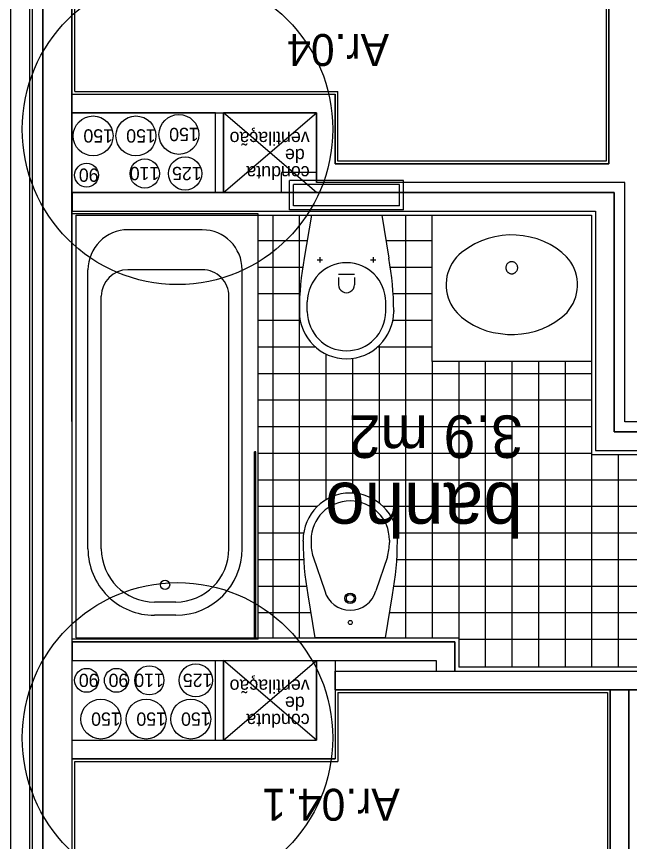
# Model space of a CAD drawing. Extents: x 1278 to 1356, y -253.7 to -224.
# Drawn here: x 1340.025 to 1342.332, y -240.985 to -237.882 of the extents above; entities that cross this region are included whole.
import ezdxf

# ---------------------------------------------------------------- set-up
doc = ezdxf.new("R2010")
doc.units = 0
for name, color, linetype in [('Level 1', 7, 'Continuous'), ('Level 10', 7, 'Continuous'), ('Level 11', 7, 'Continuous'), ('Level 2', 7, 'Continuous'), ('Level 36', 7, 'Continuous'), ('Level 40', 7, 'Continuous'), ('Level 41', 7, 'Continuous'), ('Level 60', 7, 'Continuous'), ('Level 65', 7, 'Continuous'), ('Level 66', 7, 'Continuous'), ('Level 67', 7, 'Continuous'), ('Level 69', 7, 'Continuous'), ('Level 70', 7, 'Continuous')]:
    doc.layers.add(name, color=color, linetype=linetype)

msp = doc.modelspace()

# ---------------------------------------------------------------- linework, layer by layer
at = {"layer": 'Level 1'}
for p, q in [((1340.2341, -246.584), (1340.234, -232.2657)), ((1342.254, -236.6557), (1342.254, -238.4357)), ((1340.0733, -236.7713), (1340.0733, -242.1713)), ((1340.124, -242.1713), (1340.124, -236.7713)), ((1340.234, -238.174), (1341.224, -238.174)), ((1340.234, -238.244), (1341.154, -238.244)), ((1340.774, -238.544), (1340.774, -238.244)), ((1340.804, -238.544), (1340.804, -238.244)), ((1342.254, -238.4357), (1341.224, -238.4357)), ((1341.154, -238.469), (1341.0217, -238.469)), ((1341.154, -238.499), (1341.0517, -238.499)), ((1342.314, -238.5057), (1341.154, -238.5057)), ((1342.314, -239.4057), (1342.314, -238.5057)), ((1340.234, -238.544), (1342.274, -238.544)), ((1342.274, -238.544), (1342.274, -239.444)), ((1340.234, -238.614), (1342.204, -238.614)), ((1342.204, -238.614), (1342.204, -239.514)), ((1343.314, -239.4057), (1342.314, -239.4057)), ((1342.274, -239.444), (1343.274, -239.444)), ((1342.204, -239.514), (1343.204, -239.514)), ((1340.234, -240.234), (1341.674, -240.234)), ((1341.674, -240.234), (1341.674, -240.344)), ((1340.234, -240.304), (1341.154, -240.304)), ((1340.774, -240.604), (1340.774, -240.304)), ((1340.804, -240.604), (1340.804, -240.304)), ((1341.224, -240.304), (1341.604, -240.304)), ((1341.604, -240.304), (1341.604, -240.344)), ((1341.224, -240.414), (1342.259, -240.414)), ((1342.259, -240.414), (1342.259, -242.194)), ((1342.329, -242.194), (1342.329, -240.414)), ((1342.329, -240.414), (1342.439, -240.414)), ((1340.234, -240.604), (1341.154, -240.604)), ((1340.2333, -240.674), (1341.224, -240.674))]:
    msp.add_line(p, q, dxfattribs=at)
for points in [[(1341.224, -238.4357), (1341.224, -238.174)], [(1341.154, -238.244), (1341.154, -238.5057)], [(1341.154, -240.304), (1341.154, -240.604)], [(1341.224, -240.304), (1341.224, -240.344)], [(1341.224, -240.414), (1341.224, -240.674)]]:
    msp.add_lwpolyline(points, dxfattribs=at)
at = {"layer": 'Level 10'}
for p, q in [((1340.989, -238.629), (1340.989, -240.219)), ((1341.089, -238.629), (1341.089, -240.219)), ((1341.489, -238.629), (1341.489, -240.219)), ((1340.934, -238.724), (1341.1188, -238.724)), ((1341.4146, -238.724), (1341.589, -238.724)), ((1340.934, -238.824), (1341.102, -238.824)), ((1341.4314, -238.824), (1341.589, -238.824)), ((1340.934, -238.924), (1341.0912, -238.924)), ((1341.4423, -238.924), (1341.589, -238.924)), ((1340.934, -239.024), (1341.0922, -239.024)), ((1341.4412, -239.024), (1341.589, -239.024)), ((1340.934, -239.124), (1341.1486, -239.124)), ((1341.3848, -239.124), (1341.589, -239.124)), ((1341.389, -239.1201), (1341.389, -239.7109)), ((1341.189, -239.1511), (1341.189, -239.6995)), ((1341.289, -239.1676), (1341.289, -239.6742)), ((1341.589, -239.179), (1341.589, -240.219)), ((1341.689, -239.179), (1341.689, -240.219)), ((1341.789, -239.179), (1341.789, -240.329)), ((1341.889, -239.179), (1341.889, -240.329)), ((1341.989, -239.179), (1341.989, -240.329)), ((1342.089, -239.179), (1342.089, -240.329)), ((1340.934, -239.224), (1342.189, -239.224)), ((1340.934, -239.324), (1342.189, -239.324)), ((1340.934, -239.424), (1342.189, -239.424)), ((1340.934, -239.524), (1342.189, -239.524)), ((1342.189, -239.529), (1342.189, -240.329)), ((1342.289, -239.529), (1342.289, -240.329)), ((1340.934, -239.624), (1343.189, -239.624)), ((1340.934, -239.724), (1341.1572, -239.724)), ((1341.4042, -239.724), (1343.189, -239.724)), ((1340.934, -239.824), (1341.1035, -239.824)), ((1341.4578, -239.824), (1343.099, -239.824)), ((1340.934, -239.924), (1341.1054, -239.924)), ((1341.456, -239.924), (1343.099, -239.924)), ((1340.934, -240.024), (1341.1162, -240.024)), ((1341.4452, -240.024), (1343.099, -240.024)), ((1340.934, -240.124), (1341.1328, -240.124)), ((1341.4286, -240.124), (1343.099, -240.124)), ((1341.689, -240.224), (1343.099, -240.224))]:
    msp.add_line(p, q, dxfattribs=at)
at = {"layer": 'Level 11'}
for p, q in [((1341.0517, -238.609), (1341.0517, -238.499)), ((1341.4817, -238.499), (1341.0517, -238.499)), ((1341.4667, -238.514), (1341.0667, -238.514)), ((1341.0667, -238.594), (1341.0667, -238.514)), ((1341.4667, -238.594), (1341.4667, -238.514)), ((1341.4817, -238.609), (1341.4817, -238.499)), ((1341.4817, -238.609), (1341.0517, -238.609)), ((1341.4667, -238.594), (1341.0667, -238.594)), ((1340.934, -238.624), (1340.234, -238.624)), ((1340.234, -240.224), (1340.234, -238.624)), ((1340.234, -240.229), (1340.234, -238.629)), ((1340.934, -240.224), (1340.934, -238.624)), ((1341.1344, -238.629), (1341.1077, -238.791)), ((1341.1344, -238.629), (1341.399, -238.629)), ((1341.399, -238.629), (1341.4257, -238.791)), ((1340.724, -238.684), (1340.444, -238.684)), ((1341.8518, -238.7055), (1341.8253, -238.7099)), ((1341.8784, -238.7034), (1341.8518, -238.7055)), ((1341.9051, -238.7037), (1341.8784, -238.7034)), ((1341.9316, -238.7063), (1341.9051, -238.7037)), ((1341.9578, -238.7113), (1341.9316, -238.7063)), ((1341.75, -238.7367), (1341.7268, -238.75)), ((1341.7743, -238.7256), (1341.75, -238.7367)), ((1341.7995, -238.7166), (1341.7743, -238.7256)), ((1341.8253, -238.7099), (1341.7995, -238.7166)), ((1341.9837, -238.7185), (1341.9578, -238.7113)), ((1342.0087, -238.728), (1341.9837, -238.7185)), ((1342.0327, -238.7397), (1342.0087, -238.728)), ((1341.6997, -238.7691), (1341.6897, -238.7779)), ((1341.7268, -238.75), (1341.6997, -238.7691)), ((1342.0557, -238.7534), (1342.0327, -238.7397)), ((1342.0774, -238.7691), (1342.0557, -238.7534)), ((1342.0946, -238.7851), (1342.0774, -238.7691)), ((1341.1567, -238.7972), (1341.1767, -238.7972)), ((1341.1667, -238.7872), (1341.1667, -238.8072)), ((1341.3567, -238.7972), (1341.3767, -238.7972)), ((1341.3667, -238.7872), (1341.3667, -238.8072)), ((1341.672, -238.7978), (1341.6645, -238.8089)), ((1341.6804, -238.7874), (1341.672, -238.7978)), ((1341.6897, -238.7779), (1341.6804, -238.7874)), ((1342.1032, -238.7953), (1342.0946, -238.7851)), ((1342.1109, -238.8062), (1342.1032, -238.7953)), ((1341.658, -238.8206), (1341.6525, -238.8328)), ((1341.6645, -238.8089), (1341.658, -238.8206)), ((1341.8663, -238.8248), (1341.8662, -238.8267)), ((1341.8662, -238.8267), (1341.8663, -238.8287)), ((1341.8666, -238.8228), (1341.8663, -238.8248)), ((1341.8663, -238.8287), (1341.8666, -238.8307)), ((1341.867, -238.8209), (1341.8666, -238.8228)), ((1341.8666, -238.8307), (1341.867, -238.8326)), ((1341.8676, -238.819), (1341.867, -238.8209)), ((1341.8683, -238.8172), (1341.8676, -238.819)), ((1341.8692, -238.8155), (1341.8683, -238.8172)), ((1341.8703, -238.8138), (1341.8692, -238.8155)), ((1341.8715, -238.8122), (1341.8703, -238.8138)), ((1341.8728, -238.8108), (1341.8715, -238.8122)), ((1341.8742, -238.8095), (1341.8728, -238.8108)), ((1341.8758, -238.8083), (1341.8742, -238.8095)), ((1341.8774, -238.8072), (1341.8758, -238.8083)), ((1341.8791, -238.8063), (1341.8774, -238.8072)), ((1341.8809, -238.8055), (1341.8791, -238.8063)), ((1341.8828, -238.8049), (1341.8809, -238.8055)), ((1341.8847, -238.8045), (1341.8828, -238.8049)), ((1341.8866, -238.8043), (1341.8847, -238.8045)), ((1341.8885, -238.8042), (1341.8866, -238.8043)), ((1341.8905, -238.8043), (1341.8885, -238.8042)), ((1341.8924, -238.8045), (1341.8905, -238.8043)), ((1341.8943, -238.8049), (1341.8924, -238.8045)), ((1341.8962, -238.8055), (1341.8943, -238.8049)), ((1341.898, -238.8063), (1341.8962, -238.8055)), ((1341.8997, -238.8072), (1341.898, -238.8063)), ((1341.9013, -238.8083), (1341.8997, -238.8072)), ((1341.9029, -238.8095), (1341.9013, -238.8083)), ((1341.9043, -238.8108), (1341.9029, -238.8095)), ((1341.9056, -238.8122), (1341.9043, -238.8108)), ((1341.9068, -238.8138), (1341.9056, -238.8122)), ((1341.9079, -238.8155), (1341.9068, -238.8138)), ((1341.9088, -238.8172), (1341.9079, -238.8155)), ((1341.9095, -238.819), (1341.9088, -238.8172)), ((1341.9101, -238.8209), (1341.9095, -238.819)), ((1341.9105, -238.8228), (1341.9101, -238.8209)), ((1341.9101, -238.8326), (1341.9105, -238.8307)), ((1341.9108, -238.8248), (1341.9105, -238.8228)), ((1341.9105, -238.8307), (1341.9108, -238.8287)), ((1341.9109, -238.8267), (1341.9108, -238.8248)), ((1341.9108, -238.8287), (1341.9109, -238.8267)), ((1342.1177, -238.8177), (1342.1109, -238.8062)), ((1342.1234, -238.8298), (1342.1177, -238.8177)), ((1342.1281, -238.8424), (1342.1234, -238.8298)), ((1340.294, -239.884), (1340.294, -238.834)), ((1340.724, -238.834), (1340.444, -238.834)), ((1340.874, -239.884), (1340.874, -238.834)), ((1341.2367, -238.8512), (1341.2967, -238.8512)), ((1341.6448, -238.8584), (1341.6426, -238.8716)), ((1341.6481, -238.8454), (1341.6448, -238.8584)), ((1341.6525, -238.8328), (1341.6481, -238.8454)), ((1341.867, -238.8326), (1341.8676, -238.8345)), ((1341.8676, -238.8345), (1341.8683, -238.8363)), ((1341.8683, -238.8363), (1341.8692, -238.838)), ((1341.8692, -238.838), (1341.8703, -238.8397)), ((1341.8703, -238.8397), (1341.8715, -238.8412)), ((1341.8715, -238.8412), (1341.8728, -238.8427)), ((1341.8728, -238.8427), (1341.8742, -238.844)), ((1341.8742, -238.844), (1341.8758, -238.8452)), ((1341.8758, -238.8452), (1341.8774, -238.8463)), ((1341.8774, -238.8463), (1341.8791, -238.8472)), ((1341.8791, -238.8472), (1341.8809, -238.8479)), ((1341.8809, -238.8479), (1341.8828, -238.8485)), ((1341.8828, -238.8485), (1341.8847, -238.849)), ((1341.8847, -238.849), (1341.8866, -238.8492)), ((1341.8866, -238.8492), (1341.8885, -238.8493)), ((1341.8885, -238.8493), (1341.8905, -238.8492)), ((1341.8905, -238.8492), (1341.8924, -238.849)), ((1341.8924, -238.849), (1341.8943, -238.8485)), ((1341.8943, -238.8485), (1341.8962, -238.8479)), ((1341.8962, -238.8479), (1341.898, -238.8472)), ((1341.898, -238.8472), (1341.8997, -238.8463)), ((1341.8997, -238.8463), (1341.9013, -238.8452)), ((1341.9013, -238.8452), (1341.9029, -238.844)), ((1341.9029, -238.844), (1341.9043, -238.8427)), ((1341.9043, -238.8427), (1341.9056, -238.8412)), ((1341.9056, -238.8412), (1341.9068, -238.8397)), ((1341.9068, -238.8397), (1341.9079, -238.838)), ((1341.9079, -238.838), (1341.9088, -238.8363)), ((1341.9088, -238.8363), (1341.9095, -238.8345)), ((1341.9095, -238.8345), (1341.9101, -238.8326)), ((1342.1316, -238.8553), (1342.1281, -238.8424)), ((1342.1341, -238.8685), (1342.1316, -238.8553)), ((1341.2367, -238.8635), (1341.2367, -238.8907)), ((1341.2967, -238.8635), (1341.2967, -238.8907)), ((1341.6426, -238.8716), (1341.6416, -238.8863)), ((1341.6416, -238.8863), (1341.6417, -238.9001)), ((1342.1354, -238.8831), (1342.1341, -238.8685)), ((1342.1355, -238.8969), (1342.1354, -238.8831)), ((1341.6417, -238.9001), (1341.643, -238.9135)), ((1341.643, -238.9135), (1341.6455, -238.9267)), ((1342.129, -238.9365), (1342.1323, -238.9235)), ((1342.1323, -238.9235), (1342.1345, -238.9103)), ((1342.1345, -238.9103), (1342.1355, -238.8969)), ((1340.344, -239.884), (1340.344, -238.934)), ((1340.824, -239.884), (1340.824, -238.934)), ((1341.1192, -238.9915), (1341.1192, -238.9554)), ((1341.4142, -238.9915), (1341.4142, -238.9554)), ((1341.6455, -238.9267), (1341.649, -238.9396)), ((1341.649, -238.9396), (1341.6537, -238.9521)), ((1341.6537, -238.9521), (1341.6594, -238.9642)), ((1342.1191, -238.9614), (1342.1246, -238.9492)), ((1342.1246, -238.9492), (1342.129, -238.9365)), ((1341.6594, -238.9642), (1341.6662, -238.9758)), ((1341.6662, -238.9758), (1341.6739, -238.9867)), ((1341.6739, -238.9867), (1341.6825, -238.9969)), ((1342.0967, -238.9945), (1342.1051, -238.9841)), ((1342.1051, -238.9841), (1342.1126, -238.9731)), ((1342.1126, -238.9731), (1342.1191, -238.9614)), ((1341.0892, -238.9881), (1341.0892, -238.9918)), ((1341.4442, -238.9881), (1341.4442, -238.9918)), ((1341.6825, -238.9969), (1341.6997, -239.0128)), ((1341.6997, -239.0128), (1341.7214, -239.0285)), ((1342.0503, -239.032), (1342.0774, -239.0128)), ((1342.0774, -239.0128), (1342.0874, -239.0041)), ((1342.0874, -239.0041), (1342.0967, -238.9945)), ((1341.7214, -239.0285), (1341.7444, -239.0422)), ((1341.7444, -239.0422), (1341.7684, -239.0539)), ((1342.0028, -239.0564), (1342.0271, -239.0452)), ((1342.0271, -239.0452), (1342.0503, -239.032)), ((1341.7684, -239.0539), (1341.7934, -239.0634)), ((1341.7934, -239.0634), (1341.8191, -239.0706)), ((1341.8191, -239.0706), (1341.8455, -239.0746)), ((1341.8455, -239.0746), (1341.872, -239.0772)), ((1341.872, -239.0772), (1341.8987, -239.0775)), ((1341.8987, -239.0775), (1341.9253, -239.0754)), ((1341.9253, -239.0754), (1341.9516, -239.071)), ((1341.9516, -239.071), (1341.9776, -239.0653)), ((1341.9776, -239.0653), (1342.0028, -239.0564)), ((1341.1032, -239.8548), (1341.1032, -239.8512)), ((1341.1332, -239.8515), (1341.1332, -239.8596)), ((1341.4282, -239.8515), (1341.4282, -239.8596)), ((1341.4582, -239.8548), (1341.4582, -239.8512)), ((1341.1409, -239.9145), (1341.1846, -240.0424)), ((1341.4205, -239.9145), (1341.3769, -240.0424)), ((1341.1484, -240.219), (1341.1218, -240.0569)), ((1341.413, -240.219), (1341.4397, -240.0569)), ((1340.624, -240.084), (1340.544, -240.084)), ((1340.624, -240.134), (1340.544, -240.134)), ((1340.934, -240.224), (1340.234, -240.224)), ((1341.413, -240.219), (1341.1484, -240.219))]:
    msp.add_line(p, q, dxfattribs=at)
for centre, radius in [((1340.584, -240.0195), 0.0173), ((1341.2807, -240.0701), 0.02), ((1341.2807, -240.0701), 0.0146), ((1341.2807, -240.161), 0.00766)]:
    msp.add_circle(centre, radius, dxfattribs=at)
for centre, radius, start, end in [((1340.444, -238.834), 0.15, 89.9999, 180.0002), ((1340.724, -238.834), 0.15, 360, 90), ((1341.2667, -238.9554), 0.1475, 0.0002, 179.9999), ((1340.444, -238.934), 0.1, 90.0001, 179.9999), ((1340.724, -238.934), 0.1, 360, 90.0001), ((1341.2667, -238.8905), 0.03, 179.9995, 0.0013), ((1341.2667, -238.9915), 0.1775, 180.0002, 359.9999), ((1341.2667, -238.9915), 0.1475, 180.0002, 359.9999), ((1341.2807, -239.8515), 0.1775, 0.0002, 179.9999), ((1341.2807, -239.8515), 0.1475, 0.0002, 179.9999), ((1340.544, -239.884), 0.25, 180, 270.0001), ((1340.544, -239.884), 0.2, 180, 270), ((1340.624, -239.884), 0.25, 269.9999, 359.9999), ((1340.624, -239.884), 0.2, 270, 0), ((1341.3332, -239.8596), 0.2, 180.0017, 195.9319), ((1341.2282, -239.8596), 0.2, 344.0693, 0.0006), ((1341.2807, -240.015), 0.1, 195.9317, 344.1953)]:
    msp.add_arc(centre, radius, start, end, dxfattribs=at)
for centre, major_axis, ratio, start_param, end_param in [((1342.4892, -238.9881), (-1.4, 0), 0.867931, 6.120269, 6.283188), ((1340.0442, -238.9881), (1.4, 0), 0.867931, 6.283184, 6.446103), ((1342.5032, -239.8549), (-1.4, 0), 0.88995, 6.283183, 6.446102), ((1340.0582, -239.8549), (1.4, 0), 0.88995, 6.120269, 6.283187)]:
    msp.add_ellipse(centre, major_axis=major_axis, ratio=ratio, start_param=start_param, end_param=end_param, dxfattribs=at)
at = {"layer": 'Level 2'}
for p, q in [((1341.589, -239.179), (1341.589, -238.629)), ((1342.189, -238.629), (1342.189, -239.179)), ((1342.189, -239.179), (1341.589, -239.179))]:
    msp.add_line(p, q, dxfattribs=at)
at = {"layer": 'Level 36'}
for p, q in [((1340.926, -239.519), (1340.921, -239.519)), ((1340.921, -240.219), (1340.921, -239.519)), ((1340.926, -240.219), (1340.926, -239.519))]:
    msp.add_line(p, q, dxfattribs=at)
at = {"layer": 'Level 41'}
for p, q in [((1341.154, -238.544), (1340.804, -238.244)), ((1340.804, -238.544), (1341.154, -238.244)), ((1341.154, -240.604), (1340.804, -240.304)), ((1340.804, -240.604), (1341.154, -240.304))]:
    msp.add_line(p, q, dxfattribs=at)
for centre, radius in [((1340.3133, -238.3309), 0.075), ((1340.4743, -238.3309), 0.075), ((1340.636, -238.3254), 0.075), ((1340.5076, -238.4723), 0.055), ((1340.6593, -238.4723), 0.0625), ((1340.2888, -238.4785), 0.045), ((1340.6997, -240.3785), 0.0625), ((1340.2888, -240.3785), 0.045), ((1340.4008, -240.3785), 0.045), ((1340.5248, -240.3785), 0.055), ((1340.3423, -240.5244), 0.075), ((1340.5125, -240.5244), 0.075), ((1340.6806, -240.5244), 0.075)]:
    msp.add_circle(centre, radius, dxfattribs=at)
at = {"layer": 'Level 65'}
for p, q in [((1342.244, -236.6557), (1342.244, -238.4257)), ((1340.244, -238.164), (1341.234, -238.164)), ((1342.244, -238.4257), (1341.234, -238.4257)), ((1340.249, -240.219), (1340.249, -238.629)), ((1340.249, -238.629), (1342.189, -238.629)), ((1342.189, -238.629), (1342.189, -239.529)), ((1342.189, -239.529), (1343.189, -239.529)), ((1340.249, -240.219), (1341.689, -240.219)), ((1341.689, -240.219), (1341.689, -240.329)), ((1342.439, -240.329), (1341.689, -240.329)), ((1341.234, -240.424), (1342.249, -240.424)), ((1342.249, -240.424), (1342.249, -242.194)), ((1340.244, -242.029), (1340.244, -240.684)), ((1340.244, -240.684), (1341.234, -240.684))]:
    msp.add_line(p, q, dxfattribs=at)
for points in [[(1340.244, -238.164), (1340.244, -236.8257)], [(1341.234, -238.4257), (1341.234, -238.164)], [(1341.234, -240.424), (1341.234, -240.684)]]:
    msp.add_lwpolyline(points, dxfattribs=at)
at = {"layer": 'Level 66'}
for p, q in [((1341.0217, -238.544), (1341.0217, -238.469)), ((1341.0517, -238.544), (1341.0517, -238.499)), ((1341.224, -240.344), (1341.604, -240.344)), ((1341.674, -240.344), (1342.439, -240.344))]:
    msp.add_line(p, q, dxfattribs=at)
at = {"layer": 'Level 67'}
msp.add_lwpolyline([(1345.474, -236.7713), (1345.474, -240.304), (1343.314, -240.304), (1343.314, -239.4057), (1342.314, -239.4057), (1342.314, -238.5057), (1341.154, -238.5057), (1341.154, -238.244), (1340.804, -238.244), (1340.804, -238.544), (1340.774, -238.544), (1340.774, -238.244), (1340.234, -238.244), (1340.234, -238.174), (1341.224, -238.174), (1341.224, -238.4357), (1342.254, -238.4357), (1342.254, -236.6557)], dxfattribs=at)
for points in [[(1340.0733, -242.1713), (1340.0033, -242.1713), (1340.0033, -236.7713), (1340.0733, -236.7713)], [(1340.2333, -242.1713), (1340.234, -242.1713), (1340.234, -242.109), (1340.834, -242.109), (1340.834, -242.039), (1340.234, -242.039), (1340.2333, -236.7713), (1340.124, -236.7713), (1340.124, -242.1713), (1340.234, -242.1713)], [(1345.474, -242.1713), (1345.474, -240.344), (1343.274, -240.344), (1343.274, -239.444), (1342.274, -239.444), (1342.274, -238.544), (1340.234, -238.544), (1340.234, -238.614), (1342.204, -238.614), (1342.204, -239.514), (1343.204, -239.514), (1343.204, -240.334), (1343.169, -240.334), (1343.169, -240.414), (1345.404, -240.414), (1345.404, -242.034), (1343.259, -242.034), (1343.259, -242.194), (1343.329, -242.194), (1343.329, -242.104), (1345.404, -242.104), (1345.404, -242.1713), (1345.474, -242.1713), (1345.474, -240.344)], [(1341.674, -240.344), (1341.674, -240.234), (1340.234, -240.234), (1340.234, -240.304), (1341.604, -240.304), (1341.604, -240.344)], [(1341.224, -240.304), (1341.224, -240.674), (1340.234, -240.674), (1340.234, -240.604), (1340.774, -240.604), (1340.774, -240.304), (1340.804, -240.304), (1340.804, -240.604), (1341.154, -240.604), (1341.154, -240.304)], [(1342.439, -240.344), (1342.439, -240.414), (1341.224, -240.414), (1341.224, -240.344)], [(1342.329, -240.414), (1342.329, -242.194), (1342.259, -242.194), (1342.259, -240.414)]]:
    msp.add_lwpolyline(points, close=True, dxfattribs=at)
at = {"layer": 'Level 69'}
for centre in [(1340.6308, -238.3059), (1340.6308, -240.5951)]:
    msp.add_circle(centre, 0.5842, dxfattribs=at)
at = {"layer": 'Level 70'}
msp.add_line((1340.084, -229.6198), (1340.084, -250.7923), dxfattribs=at)

# ---------------------------------------------------------------- texts
at = {"layer": 'Level 40'}
for s, p in [('Ar.04', (1341.4269, -237.9477)), ('Ar.04.1', (1341.4672, -240.7863))]:
    msp.add_text(s, height=0.12, rotation=180, dxfattribs=at).set_placement(p)
at = {"layer": 'Level 41'}
for s, p in [('150', (1340.711, -238.3004)), ('ventilação ', (1341.128, -238.3155)), ('150', (1340.3883, -238.3059)), ('150', (1340.5493, -238.3059)), (' de ', (1341.128, -238.3799)), ('90', (1340.3338, -238.4535)), ('110', (1340.5626, -238.4473)), ('125', (1340.7218, -238.4473)), ('conduta', (1341.128, -238.4444)), ('90', (1340.3338, -240.3535)), ('90', (1340.4458, -240.3535)), ('110', (1340.5798, -240.3535)), ('125', (1340.7622, -240.3535)), ('ventilação ', (1341.128, -240.3755)), (' de ', (1341.128, -240.4399)), ('150', (1340.4173, -240.4994)), ('150', (1340.5875, -240.4994)), ('150', (1340.7556, -240.4994)), ('conduta', (1341.128, -240.5044))]:
    msp.add_text(s, height=0.05, rotation=180, dxfattribs=at).set_placement(p)
at = {"layer": 'Level 60'}
for s, height, p in [('3.9 m2', 0.16, (1341.93, -239.3821)), ('banho', 0.2, (1341.9297, -239.6356))]:
    msp.add_text(s, height=height, rotation=180, dxfattribs=at).set_placement(p)

doc.saveas('drawing.dxf')
